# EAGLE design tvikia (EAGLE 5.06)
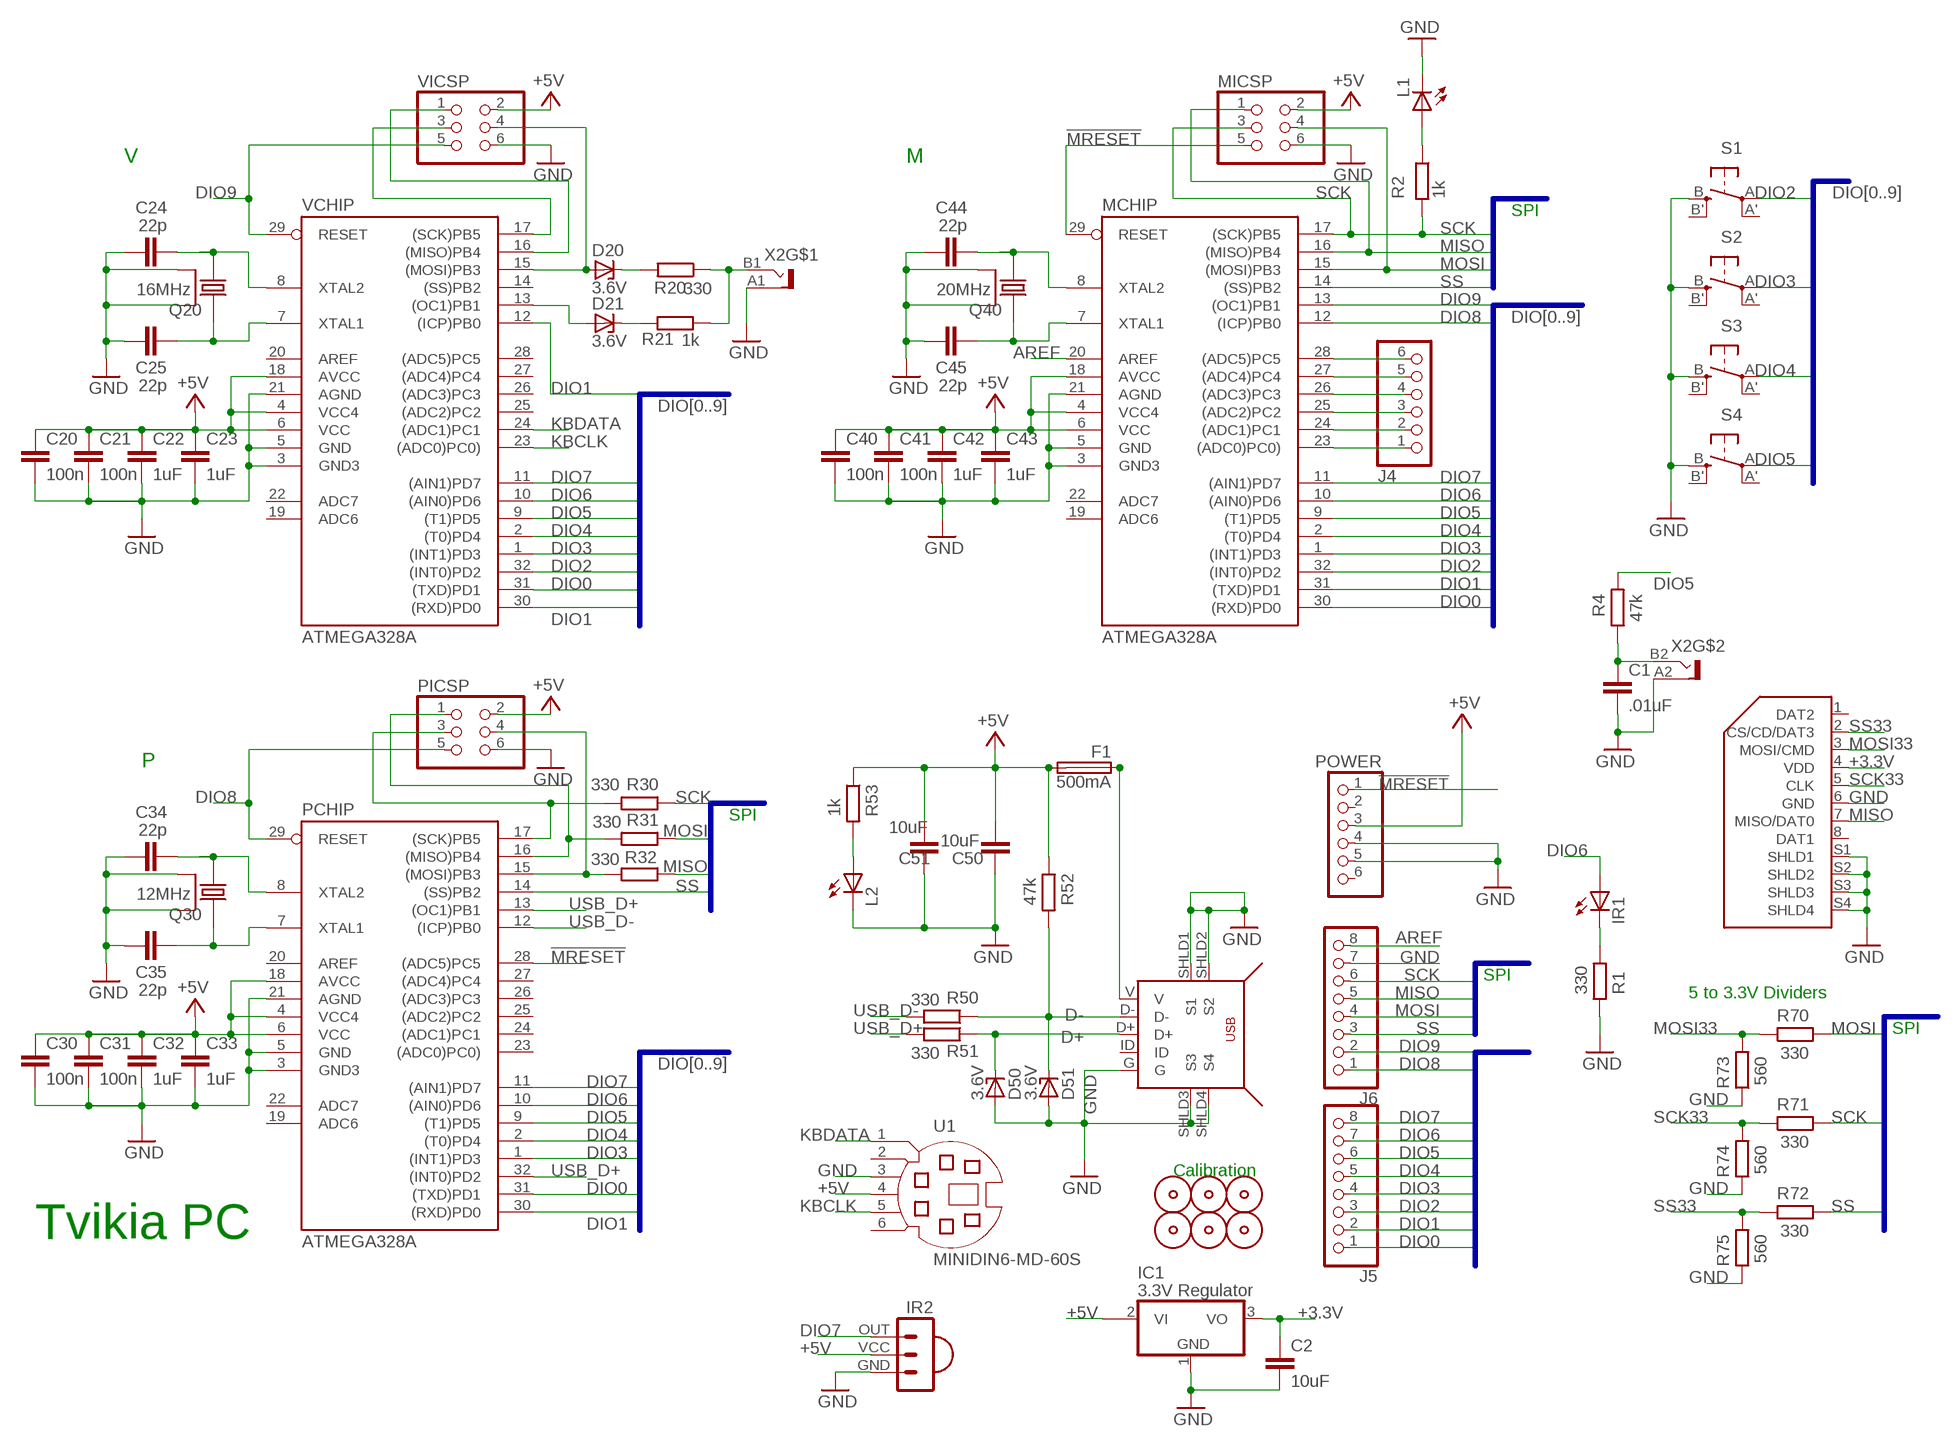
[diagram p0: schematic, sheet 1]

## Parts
C1  .01uF  C-EUC0603  [C0603]
C2  10uF  C-EUC0603  [C0603]
C20  100n  C-EUC0603  [C0603]
C21  100n  C-EUC0603  [C0603]
C22  1uF  C-EUC0603  [C0603]
C23  1uF  C-EUC0603  [C0603]
C24  22p  C-EUC0603  [C0603]
C25  22p  C-EUC0603  [C0603]
C30  100n  C-EUC0603  [C0603]
C31  100n  C-EUC0603  [C0603]
C32  1uF  C-EUC0603  [C0603]
C33  1uF  C-EUC0603  [C0603]
C34  22p  C-EUC0603  [C0603]
C35  22p  C-EUC0603  [C0603]
C40  100n  C-EUC0603  [C0603]
C41  100n  C-EUC0603  [C0603]
C42  1uF  C-EUC0603  [C0603]
C43  1uF  C-EUC0603  [C0603]
C44  22p  C-EUC0603  [C0603]
C45  22p  C-EUC0603  [C0603]
C50  10uF  C-EUC0603  [C0603]
C51  10uF  C-EUC0603  [C0603]
D20  3.6V  ZENER-DIODESOT23  [SOT23]
D21  3.6V  ZENER-DIODESOT23  [SOT23]
D50  3.6V  ZENER-DIODESOT23  [SOT23]
D51  3.6V  ZENER-DIODESOT23  [SOT23]
F1  500mA  FUSE0402  [0402]
IC1  3.3V Regulator  MCP170312MB  [SOT89]
IR1  LED5MM  [LED5MM]
IR2  IR-RECV-TSOP323  [IR-RECV-TSOP323]
J4  PINHD-1X6-CIRC  [1X06]
J5  PINHD-1X8-CIRC  [1X08]
J6  PINHD-1X8-CIRC  [1X08]
L1  LEDCHIP-LED0603  [CHIP-LED0603]
L2  LEDCHIPLED_0603  [CHIPLED_0603]
MCHIP  ATMEGA328A  [TQFP32-08]
MICSP  PINHD-2X3  [2X03]
PCHIP  ATMEGA328A  [TQFP32-08]
PICSP  PINHD-2X3  [2X03]
POWER  PINHD-1X6-CIRC  [1X06]
Q20  16MHz  NX3225SA  [NX3225SA]
Q30  12MHz  NX3225SA  [NX3225SA]
Q40  20MHz  NX3225SA  [NX3225SA]
R1  330  R-EU_R0603  [R0603]
R2  1k  R-EU_R0603  [R0603]
R4  47k  R-EU_R0603  [R0603]
R20  330  R-EU_R0603  [R0603]
R21  1k  R-EU_R0603  [R0603]
R30  330  R-EU_R0603  [R0603]
R31  330  R-EU_R0603  [R0603]
R32  330  R-EU_R0603  [R0603]
R50  330  R-EU_R0603  [R0603]
R51  330  R-EU_R0603  [R0603]
R52  47k  R-EU_R0603  [R0603]
R53  1k  R-EU_R0603  [R0603]
R70  330  R-EU_R0603  [R0603]
R71  330  R-EU_R0603  [R0603]
R72  330  R-EU_R0603  [R0603]
R73  560  R-EU_R0603  [R0603]
R74  560  R-EU_R0603  [R0603]
R75  560  R-EU_R0603  [R0603]
S1  EVQ-Q2P02W  [EVQ-Q2P02W]
S2  EVQ-Q2P02W  [EVQ-Q2P02W]
S3  EVQ-Q2P02W  [EVQ-Q2P02W]
S4  EVQ-Q2P02W  [EVQ-Q2P02W]
U1  MINIDIN6-MD-60S  [MINIDIN6-MD-60S]
U$1  CALIBRATION-MARK  [CALIBRATION-MARK]
U$4  CALIBRATION-MARK  [CALIBRATION-MARK]
U$5  CALIBRATION-MARK  [CALIBRATION-MARK]
U$6  CALIBRATION-MARK  [CALIBRATION-MARK]
U$8  MICROUSB-ZX62-B-5PA  [MICROUSB-ZX62-B-5PA]
U$9  MICROSD_3M_2900  [MICROSD_3M_2900]
U$10  CALIBRATION-MARK  [CALIBRATION-MARK]
U$12  CALIBRATION-MARK  [CALIBRATION-MARK]
VCHIP  ATMEGA328A  [TQFP32-08]
VICSP  PINHD-2X3  [2X03]
X2  DUAL-PHONO-161-4218-E  [DUAL-PHONO-161-4218-E]

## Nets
!MRESET: MCHIP.29(RESET) MICSP.5 PCHIP.28((ADC5)PC5) POWER.1
+3.3V: C2.1 IC1.3(VO) U$9.4(VDD)
+5V: C20.1 C21.1 C22.1 C23.1 C30.1 C31.1 C32.1 C33.1 C40.1 C41.1 C42.1 C43.1 C50.1 C51.1 F1.2 IC1.2@1(VI1) IR2.VCC MCHIP.4(VCC4) MCHIP.6(VCC) MCHIP.18(AVCC) MICSP.2 PCHIP.4(VCC4) PCHIP.6(VCC) PCHIP.18(AVCC) PICSP.2 POWER.3 R52.1 R53.1 U1.4 VCHIP.4(VCC4) VCHIP.6(VCC) VCHIP.18(AVCC) VICSP.2
AREF: J6.8 MCHIP.20(AREF)
D+: D50.3(C) R51.1 U$8.D+
D-: D51.3(C) R50.1 R52.2 U$8.D-
DIO0: J5.1 MCHIP.30((RXD)PD0) PCHIP.31((TXD)PD1) VCHIP.31((TXD)PD1)
DIO1: J5.2 MCHIP.31((TXD)PD1) PCHIP.30((RXD)PD0) VCHIP.12((ICP)PB0) VCHIP.30((RXD)PD0)
DIO2: J5.3 MCHIP.32((INT0)PD2) S1.A(P) VCHIP.32((INT0)PD2)
DIO3: J5.4 MCHIP.1((INT1)PD3) PCHIP.1((INT1)PD3) S2.A(P) VCHIP.1((INT1)PD3)
DIO4: J5.5 MCHIP.2((T0)PD4) PCHIP.2((T0)PD4) S3.A(P) VCHIP.2((T0)PD4)
DIO5: J5.6 MCHIP.9((T1)PD5) PCHIP.9((T1)PD5) R4.2 S4.A(P) VCHIP.9((T1)PD5)
DIO6: IR1.A J5.7 MCHIP.10((AIN0)PD6) PCHIP.10((AIN0)PD6) VCHIP.10((AIN0)PD6)
DIO7: IR2.OUT J5.8 MCHIP.11((AIN1)PD7) PCHIP.11((AIN1)PD7) VCHIP.11((AIN1)PD7)
DIO8: J6.1 MCHIP.12((ICP)PB0) PCHIP.29(RESET) PICSP.5
DIO9: J6.2 MCHIP.13((OC1)PB1) VCHIP.29(RESET) VICSP.5
GND [power]: C1.2 C2.2 C20.2 C21.2 C22.2 C23.2 C24.1 C25.1 C30.2 C31.2 C32.2 C33.2 C34.1 C35.1 C40.2 C41.2 C42.2 C43.2 C44.1 C45.1 C50.2 C51.2 D50.1(A) D51.1(A) IC1.1(GND) IR2.GND J6.7 L1.C L2.C MCHIP.3(GND3) MCHIP.5(GND) MCHIP.21(AGND) MICSP.6 PCHIP.3(GND3) PCHIP.5(GND) PCHIP.21(AGND) PICSP.6 POWER.4 POWER.5 Q20.2(GND2) Q20.4(GND) Q30.2(GND2) Q30.4(GND) Q40.2(GND2) Q40.4(GND) R1.2 R73.1 R74.1 R75.1 S1.B(S) S2.B(S) S3.B(S) S4.B(S) U1.3 U$8.G U$8.SHLD1(S1) U$8.SHLD2(S2) U$8.SHLD3(S3) U$8.SHLD4(S4) U$9.6(GND) U$9.S1(SHLD1) U$9.S2(SHLD2) U$9.S3(SHLD3) U$9.S4(SHLD4) VCHIP.3(GND3) VCHIP.5(GND) VCHIP.21(AGND) VICSP.6 X2.A1 X2.A2
KBCLK: U1.5 VCHIP.23((ADC0)PC0))
KBDATA: U1.1 VCHIP.24((ADC1)PC1)
MISO: J6.5 MCHIP.16((MISO)PB4) MICSP.1 R32.1 U$9.7(MISO/DAT0)
MOSI: J6.4 MCHIP.15((MOSI)PB3) MICSP.4 R31.1 R70.2
MOSI33: R70.1 R73.2 U$9.3(MOSI/CMD)
N$2: IR1.K(C) R1.1
N$3: L2.A R53.2
N$4: C34.2 PCHIP.8(XTAL2) Q30.1
N$5: C1.1 R4.1 X2.B2
N$8: F1.1 U$8.V
N$9: VCHIP.16((MISO)PB4) VICSP.1
N$10: C24.2 Q20.1 VCHIP.8(XTAL2)
N$11: C25.2 Q20.3 VCHIP.7(XTAL1)
N$12: D20.3(C) R20.2
N$13: D21.1(A) VCHIP.13((OC1)PB1)
N$14: D21.3(C) R21.1
N$15: R20.1 R21.2 X2.B1
N$23: C35.2 PCHIP.7(XTAL1) Q30.3
N$24: VCHIP.17((SCK)PB5) VICSP.3
N$28: C44.2 MCHIP.8(XTAL2) Q40.1
N$29: C45.2 MCHIP.7(XTAL1) Q40.3
N$30: J4.1 MCHIP.23((ADC0)PC0))
N$31: J4.2 MCHIP.24((ADC1)PC1)
N$32: J4.3 MCHIP.25((ADC2)PC2)
N$33: J4.4 MCHIP.26((ADC3)PC3)
N$34: J4.5 MCHIP.27((ADC4)PC4)
N$35: J4.6 MCHIP.28((ADC5)PC5)
N$37: L1.A R2.1
PIXEL1: D20.1(A) VCHIP.15((MOSI)PB3) VICSP.4
PMISO: PCHIP.15((MOSI)PB3) PICSP.4 R32.2
PMOSI: PCHIP.16((MISO)PB4) PICSP.1 R31.2
PSCK: PCHIP.17((SCK)PB5) PICSP.3 R30.2
SCK: J6.6 MCHIP.17((SCK)PB5) MICSP.3 R2.2 R30.1 R71.2
SCK33: R71.1 R74.2 U$9.5(CLK)
SS: J6.3 MCHIP.14((SS)PB2) PCHIP.14((SS)PB2) R72.2
SS33: R72.1 R75.2 U$9.2(CS/CD/DAT3)
USB_D+: PCHIP.13((OC1)PB1) PCHIP.32((INT0)PD2) R51.2
USB_D-: PCHIP.12((ICP)PB0) R50.2
Unconnected: IC1.2(VI) MCHIP.19(ADC6) MCHIP.22(ADC7) PCHIP.19(ADC6) PCHIP.20(AREF) PCHIP.22(ADC7) PCHIP.23((ADC0)PC0)) PCHIP.24((ADC1)PC1) PCHIP.25((ADC2)PC2) PCHIP.26((ADC3)PC3) PCHIP.27((ADC4)PC4) POWER.2 POWER.6 S1.A'(P1) S1.B'(S1) S2.A'(P1) S2.B'(S1) S3.A'(P1) S3.B'(S1) S4.A'(P1) S4.B'(S1) U1.2 U1.6 U$8.ID U$9.1(DAT2) U$9.8(DAT1) VCHIP.14((SS)PB2) VCHIP.19(ADC6) VCHIP.20(AREF) VCHIP.22(ADC7) VCHIP.25((ADC2)PC2) VCHIP.26((ADC3)PC3) VCHIP.27((ADC4)PC4) VCHIP.28((ADC5)PC5)

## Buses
DIO[0..9]
SPI:SCK,MOSI,MISO,SS

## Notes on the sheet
- V | M
- SPI
- P
- SPI
- SPI
- 5 to 3.3V Dividers
- SPI
- Calibration
- Tvikia PC

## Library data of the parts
C1 C2 C20-C25 C30-C35 C40-C45 C50 C51 = rcl:C-EU: CAPACITOR, European symbol
D20 D21 D50 D51 = diode:ZENER-DIODE: Z-Diode
F1 = tvikia:FUSE0402
IC1 = linear:MCP1703*: 250 mA, 16V, Low Quiescent Current LDO Regulator Source: http://ww1.microchip.com/downloads/en/DeviceDoc/22049b.pdf
IR1 L1 L2 = led:LED: LED
IR2 = tvikia:IR-RECV-TSOP323
J4 POWER = tvikia:PINHD-1X6-CIRC: PIN HEADER
J5 J6 = tvikia:PINHD-1X8-CIRC: PIN HEADER
MCHIP PCHIP VCHIP = tvikia:ATMEGA328: MICROCONTROLLER 4 Kbytes FLASH 128 bytes SRAM 256 bytes EEPROM UART 6-channel 10 bit ADC
MICSP PICSP VICSP = pinhead:PINHD-2X3: PIN HEADER
Q20 Q30 Q40 = tvikia:NX3225SA
R1 R2 R4 R20 R21 R30-R32 R50-R53 R70-R75 = rcl:R-EU_: RESISTOR, European symbol
S1-S4 = tvikia:EVQ-Q2P02W
U1 = tvikia:MINIDIN6-MD-60S
U$1 U$4-U$6 U$10 U$12 = tvikia:CALIBRATION-MARK: Calibration mark for board pick-n-place.
U$8 = tvikia:MICROUSB-ZX62-B-5PA
U$9 = tvikia:MICROSD_3M_2900
X2 = tvikia:DUAL-PHONO-161-4218-E

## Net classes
0 default: width 0.203 mm, drill 0.305 mm, clearance 0.203 mm
1 power: width 0.356 mm, drill 0.305 mm, clearance 0.203 mm
2 gnd: width 0.356 mm, drill 0.305 mm, clearance 0.203 mm

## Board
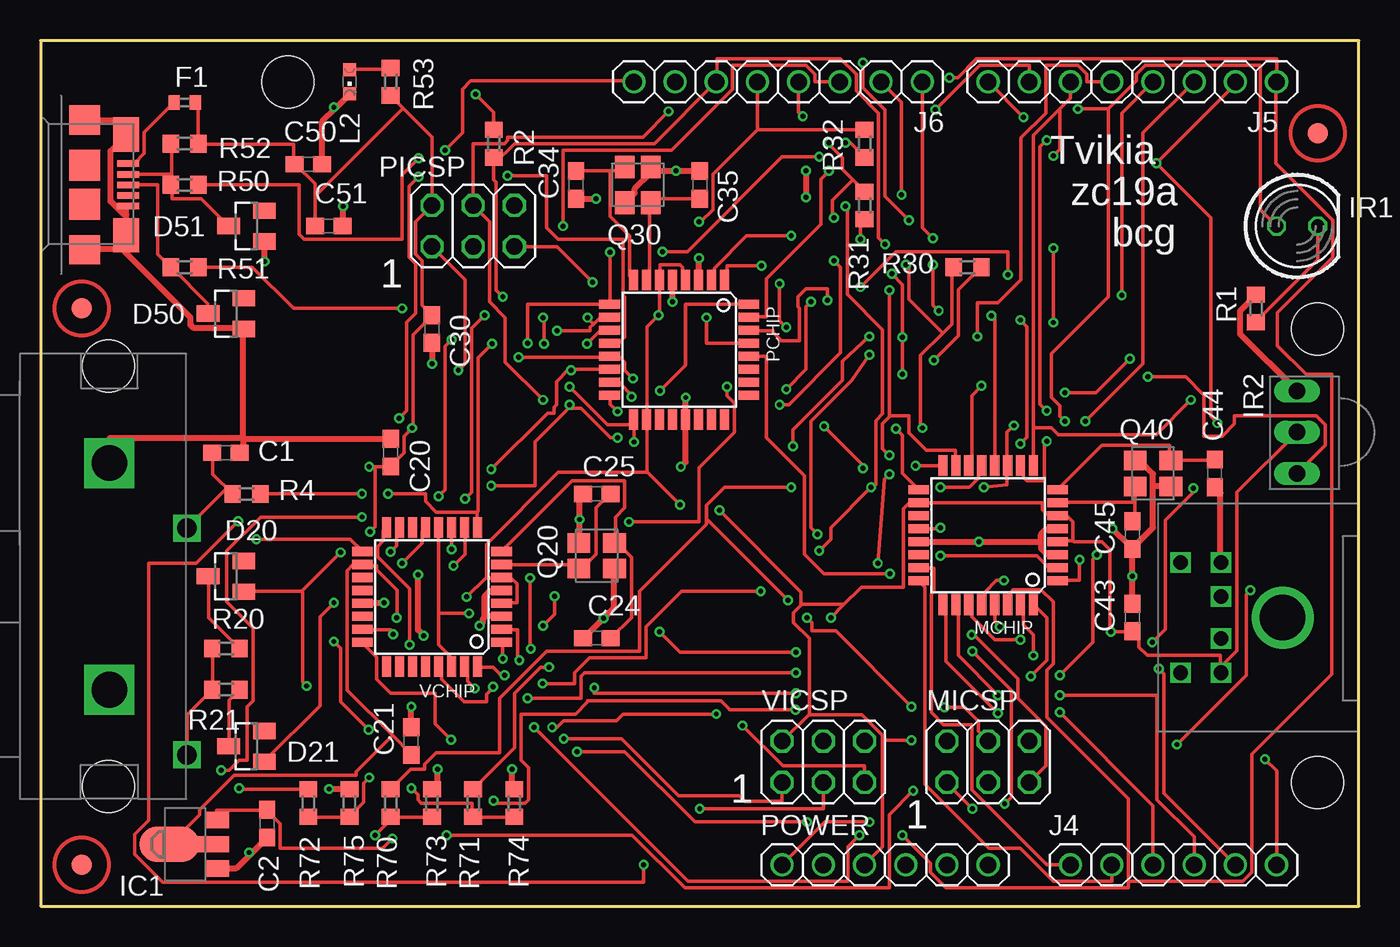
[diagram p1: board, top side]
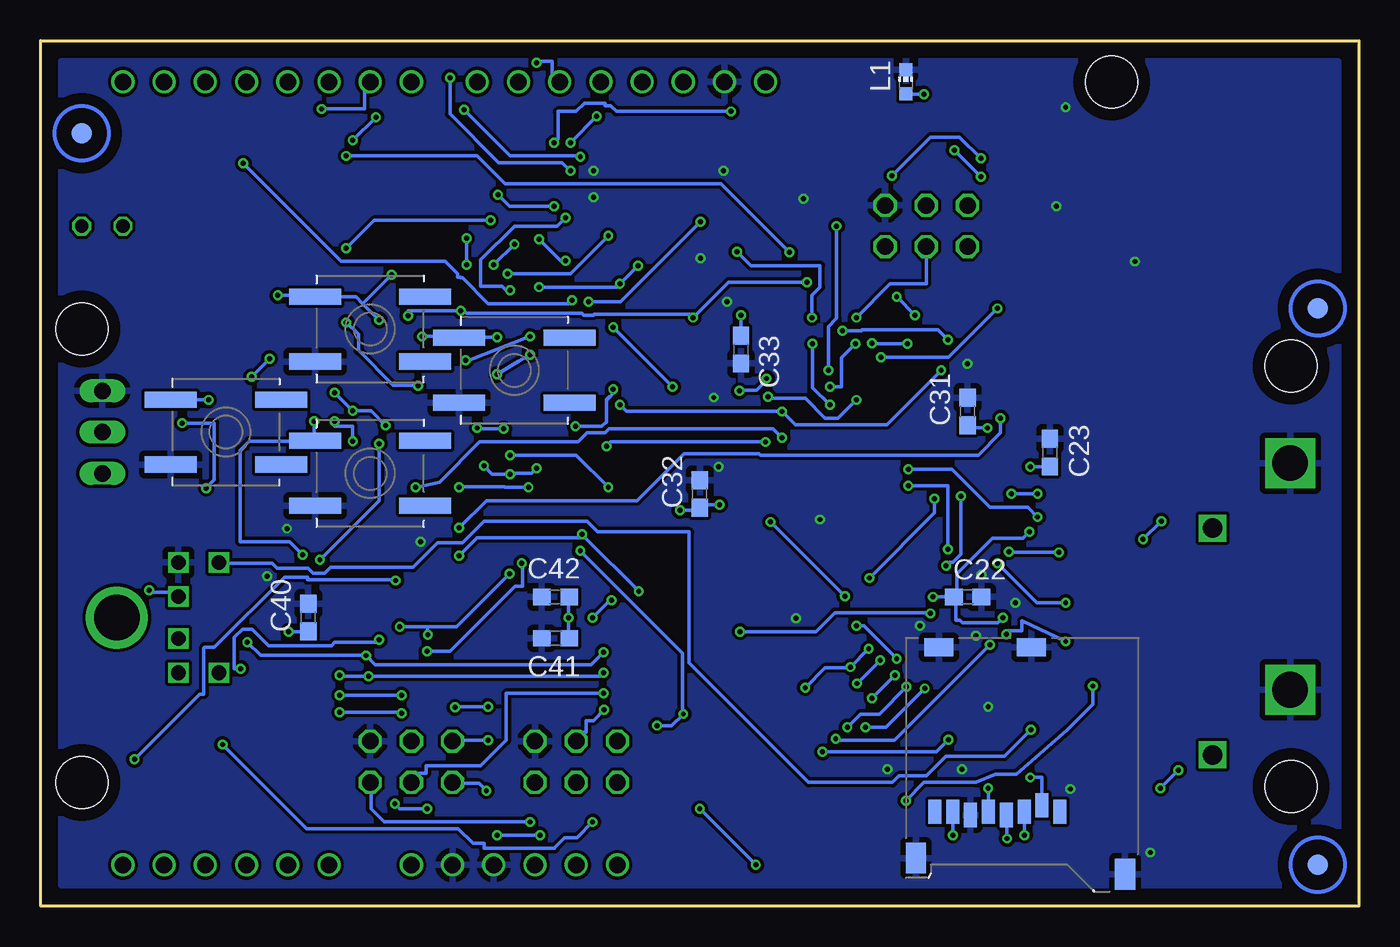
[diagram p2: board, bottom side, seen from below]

Size 81.28 x 53.34 mm. Coordinates in mm from the lower left corner, seen from the top.
Outline: 0,0 81.28,0 81.28,53.34 0,53.34 0,0
Copper layers (1*16): Top 0.035mm / dielectric 1.5mm / Bottom 0.035mm
Design rules "chung_nam_design_rules *": minimum track width 8mil, minimum drill 12mil, track to track 8mil, track to pad 8mil, pad to pad 5mil, via to via 15mil, smd to smd 5mil, copper to edge 30mil, drill to drill 30mil, minimum pad ring 7mil, minimum via ring 6mil, stop-mask expansion 3mil, vias tented up to drill 0mil, thermal gap 14mil
Holes 3.2 mm at 15.24,50.8 78.74,35.56 78.74,7.62

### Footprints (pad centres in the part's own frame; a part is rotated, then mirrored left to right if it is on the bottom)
C0603 = smd 1.1 x 1: 1 -0.85,0; 2 0.85,0
SOT23 = smd 1 x 1.4: 1 -0.95,-1.1; 2 0.95,-1.1; 3 0,1.1
0402 = smd 0.7 x 0.9: 1 -0.65,0; 2 0.65,0
SOT89 = smd 1 x 1.5: 1 -1.499,-1.981; 3 1.499,-1.981 | smd 1 x 2: 2 0,-1.727 | smd 2.2 x 3.7: 2@1 0,0.94
LED5MM = drill 0.813 octagon: A -1.27,0; K 1.27,0
IR-RECV-TSOP323 = drill 1.016 long: GND -2.54,0; OUT 2.54,0; VCC 0,0
1X06 = drill 1.016 round: 1 -6.35,0; 2 -3.81,0; 3 -1.27,0; 4 1.27,0; 5 3.81,0; 6 6.35,0
1X08 = drill 1.016 round: 1 -8.89,0; 2 -6.35,0; 3 -3.81,0; 4 -1.27,0; 5 1.27,0; 6 3.81,0; 7 6.35,0; 8 8.89,0
CHIP-LED0603 = smd 0.8 x 0.8: A 0,-0.75; C 0,0.75
CHIPLED_0603 = smd 0.8 x 0.8: A 0,-0.75; C 0,0.75
TQFP32-08 = smd 1.27 x 0.559: 1 -4.293,2.8; 2 -4.293,2; 3 -4.293,1.2; 4 -4.293,0.4; 5 -4.293,-0.4; 6 -4.293,-1.2; 7 -4.293,-2; 8 -4.293,-2.8; 17 4.293,-2.8; 18 4.293,-2; 19 4.293,-1.2; 20 4.293,-0.4; 21 4.293,0.4; 22 4.293,1.2; 23 4.293,2; 24 4.293,2.8 | smd 0.559 x 1.27: 9 -2.8,-4.293; 10 -2,-4.293; 11 -1.2,-4.293; 12 -0.4,-4.293; 13 0.4,-4.293; 14 1.2,-4.293; 15 2,-4.293; 16 2.8,-4.293; 25 2.8,4.293; 26 2,4.293; 27 1.2,4.293; 28 0.4,4.293; 29 -0.4,4.293; 30 -1.2,4.293; 31 -2,4.293; 32 -2.8,4.293
2X03 = drill 1.016 octagon: 1 -2.54,-1.27; 2 -2.54,1.27; 3 0,-1.27; 4 0,1.27; 5 2.54,-1.27; 6 2.54,1.27
NX3225SA = smd 1.4 x 1.2: 1 -1.1,-0.8; 2 1.1,-0.8; 3 1.1,0.8; 4 -1.1,0.8
R0603 = smd 1 x 1.1: 1 -0.85,0; 2 0.85,0
EVQ-Q2P02W = smd 3.2 x 1: A -3.4,2; A' 3.4,2; B -3.4,-2; B' 3.4,-2
MINIDIN6-MD-60S = drill 0.9 square: 1 -1.3,-8.5; 2 1.3,-8.5; 3 -3.4,-8.5; 4 3.4,-8.5; 5 -3.4,-11; 6 3.4,-11 | drill 2.8 round: P$7 0,-4.7
CALIBRATION-MARK = smd 1.27 x 1.27: P$1 0,0
MICROUSB-ZX62-B-5PA = smd 0.4 x 1.35: D+ 0,4.13; D- -0.65,4.13; G 1.3,4.13; ID 0.65,4.13; V -1.3,4.13 | smd 1.9 x 1.9: P$8 1.2,1.45; P$9 -1.2,1.45 | smd 2.1 x 1.6: SHLD1 -3.1,4; SHLD2 3.1,4 | smd 1.8 x 1.9: SHLD3 -4,1.45; SHLD4 4,1.45
MICROSD_3M_2900 = smd 0.8 x 1.5: 1 -9.5,10.7; 2 -8.4,10.3; 3 -7.3,10.7; 4 -6.2,10.9; 5 -5.1,10.7; 6 -4,10.9; 7 -2.9,10.7; 8 -1.8,10.7 | smd 1.24 x 1.9: S1 -13.52,14.55; S2 -0.62,13.55 | smd 1.8 x 1.1: S3 -7.75,0.55; S4 -2.05,0.55
DUAL-PHONO-161-4218-E = drill 2.2 square: A1 -6.985,-5.512; A2 6.985,-5.512 | drill 1.2 square: B1 -10.998,-10.287; B2 2.972,-10.287 | hole 3.2: -12.954,-5.461; 12.954,-5.461

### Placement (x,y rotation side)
C1  11.43,27.94 0 top
C2  13.97,5.08 270 top
C20  21.59,27.94 90 top
C21  22.86,10.16 90 top
C22  24.13,19.05 0 bottom
C23  19.05,27.94 90 bottom
C24  34.29,16.51 0 top
C25  34.29,25.4 0 top
C30  24.13,35.56 270 top
C31  24.13,30.48 90 bottom
C32  40.64,25.4 90 bottom
C33  38.1,34.29 270 bottom
C34  33.02,44.45 90 top
C35  40.64,44.45 270 top
C40  64.77,17.78 90 bottom
C41  49.53,16.51 180 bottom
C42  49.53,19.05 180 bottom
C43  67.31,17.78 90 top
C44  72.39,26.67 90 top
C45  67.31,22.86 90 top
C50  16.51,45.72 0 top
C51  17.78,41.91 0 top
D20  11.43,20.32 90 top
D21  12.7,9.84 90 top
D50  11.43,36.51 90 top
D51  12.7,41.91 90 top
F1  8.89,49.53 0 top
IC1  8.89,3.81 90 top
IR1  77.47,41.91 0 top
IR2  77.47,29.21 270 top
J4  69.85,2.54 0 top
J5  67.31,50.8 180 top
J6  45.47,50.8 180 top
L1  27.94,50.8 0 bottom
L2  19.05,50.8 180 top
MCHIP  58.42,22.86 180 top
MICSP  58.42,8.89 0 top
PCHIP  39.37,34.29 270 top
PICSP  26.67,41.91 0 top
POWER  52.07,2.54 0 top
Q20  34.29,21.59 180 top
Q30  36.83,44.45 270 top
Q40  68.58,26.67 180 top
R1  74.93,36.83 90 top
R2  27.94,46.99 270 top
R4  12.7,25.4 0 top
R20  11.43,15.88 0 top
R21  11.43,13.34 180 top
R30  57.15,39.37 0 top
R31  50.8,43.18 270 top
R32  50.8,46.99 270 top
R50  8.89,44.45 0 top
R51  8.89,39.37 0 top
R52  8.89,46.99 180 top
R53  21.59,50.8 90 top
R70  21.59,6.35 90 top
R71  26.67,6.35 90 top
R72  16.51,6.35 90 top
R73  24.13,6.35 270 top
R74  29.21,6.35 270 top
R75  19.05,6.35 270 top
S1  60.96,26.67 0 bottom
S2  60.96,35.56 0 bottom
S3  52.07,33.02 0 bottom
S4  69.85,29.21 0 bottom
U1  81.28,17.78 270 top
U$1  78.74,47.62 0 bottom
U$4  2.54,2.54 0 top
U$5  78.74,47.62 0 top
U$6  2.54,36.83 0 top
U$8  1.27,44.45 270 top
U$9  27.94,16.51 180 bottom
U$10  2.54,2.54 0 bottom
U$12  2.54,36.83 0 bottom
VCHIP  24.13,19.05 180 top
VICSP  48.26,8.89 0 top
X2  -1.27,20.32 90 top

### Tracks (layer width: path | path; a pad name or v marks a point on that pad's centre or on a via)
!MRESET  (via drill 0.3)
  Top 0.203: POWER.1 48.36,5.18 v51.1,5.18 | v52.38,20.47 48.31,20.47 47.09,21.69 47.09,26.52 44.76,28.85 44.76,33.88 43.69,33.88 PCHIP.28 | v59.13,17.22 58.83,17.53 58.83,18.54 MCHIP.29 | MICSP.5 61.98,8.64 61.98,11.07 60.25,12.8 60.25,14.02 57.56,16.71 v57.4,16.71
  Bottom 0.203: v51.1,5.18 60.1,5.18 60.91,5.99 60.91,7.62 MICSP.5 | v52.38,20.47 55.63,17.22 57.4,17.22 | 57.4,17.22 v59.13,17.22 | v57.4,16.71 57.4,17.22
+3.3V  (via drill 0.3)
  Top 0.203: IC1.3 10.87,5.33 10.87,5.89 13.97,5.89 C2.1 14.02,5.84 14.78,5.08 14.78,3.56 21.08,3.56 v21.69,4.17
  Bottom 0.203: v21.69,4.17 21.69,5.59 U$9.4
+5V  (via drill 0.3)
  Top 0.203: 20.62,27.08 21.59,27.08 C20.1 21.64,27.18 22.4,27.94 22.4,28.96 v22.91,29.46 22.96,29.52 22.96,35.2 24.13,36.37 C30.1 24.08,36.47 23.52,37.03 23.52,39.78 23.11,40.18 23.11,42.16 PICSP.2 24.13,47.4 22.35,49.17 | 20.62,27.08 v20.27,27.08 | 22.35,49.17 21.59,49.94 R53.1 | F1.2 9.7,49.38 9.7,46.99 R52.1 9.8,46.94 15.6,46.94 15.6,45.77 C50.1 15.7,45.72 16.92,44.5 16.92,43.79 | 16.92,43.79 16.92,41.91 C51.1 | 22.35,49.17 16.97,43.79 16.92,43.79 | 21.69,10.52 18.9,13.31 18.9,20.68 19.25,21.03 19.81,21.03 VCHIP.18 19.91,20.98 20.73,20.98 20.73,20.73 22,19.46 22,17.83 v21.95,17.78 | 21.69,10.52 22.86,9.35 C21.1 | IC1.2@1 7.98,3.81 9.8,5.64 9.8,5.94 11.94,8.08 19.46,8.08 19.46,8.28 21.69,10.52 | PCHIP.4 39.73,38.61 39.57,38.76 39.57,39.37 39.42,39.52 38.2,39.52 38.2,38.66 PCHIP.6 38.15,38.56 38.15,36.47 v38.1,36.42 37.39,35.71 37.39,30.07 PCHIP.18 37.39,29.97 37.39,26.77 | v26.26,19.05 27.43,20.22 | 27.43,20.22 28.4,20.22 VCHIP.6 28.5,20.22 29.01,20.22 29.36,19.86 29.36,18.69 28.45,18.69 VCHIP.4 | 37.39,26.77 v39.42,24.74 | 27.43,20.22 27.48,20.27 27.48,22.3 31.9,26.72 37.34,26.72 37.39,26.77 | IR2.VCC 73.76,25.5 73.76,15.75 72.8,14.78 U1.4 72.75,14.43 72.75,15.44 68.22,15.44 67.72,15.95 67.72,16.51 67.36,16.87 C43.1 67.31,16.92 v65.99,16.92 65.94,16.97 65.94,21.95 65.43,22.45 63.7,22.45 63.65,22.5 | 63.65,22.5 62.74,22.5 MCHIP.4 | 63.65,22.5 63.65,23.67 63.3,24.03 62.74,24.03 MCHIP.6 62.64,24.08 62.13,24.08 61.77,24.43 61.77,24.84 54.15,24.84 MCHIP.18 54.05,24.79 53.49,24.79 53.19,24.49 53.19,19.66 50.6,19.66 49.48,18.54 | 49.48,18.54 v48.72,17.78
  Top 0.203: 47.4,11.84 VICSP.2 | 47.4,11.84 47.4,16.51 46.43,17.48 46.43,18.09 46.94,18.59 | 46.94,18.59 49.43,18.59 49.48,18.54 | POWER.3 51.92,3.66 51.92,10.21 | 51.92,10.21 51.92,10.52 50.65,11.79 47.45,11.79 47.4,11.84 | 51.92,10.21 v53.7,10.21 | v41.86,24.38 46.89,19.36 46.89,18.64 46.94,18.59 | v20.32,23.06 20.62,23.37 20.62,27.08
  Bottom 0.203: v20.27,27.08 19.05,27.08 C23.1 | v22.91,29.46 23.98,29.46 24.13,29.62 C31.1 | v38.1,36.42 C33.1 | C22.1 v26.26,19.05 | v39.42,24.74 40.49,24.74 40.64,24.59 C32.1 40.69,24.49 40.79,24.38 v41.86,24.38 | v65.99,16.92 64.77,16.92 C40.1 | C41.1 48.72,16.51 v48.72,17.78 48.72,19.05 C42.1 | MICSP.2 55.83,10.21 v53.7,10.21 | v21.95,17.78 22.25,17.48 24.43,17.48 24.59,17.63 24.84,17.63 24.84,19 24.89,19 C22.1 | v20.32,23.06 20.73,22.66 22.61,22.66 24.79,20.47 24.79,19.05 C22.1
AREF  (via drill 0.3)
  Top 0.203: v55.47,23.32 55.47,23.27 54.15,23.27 MCHIP.20 | v22.1,30.07 22.55,30.53 22.55,35.97 23.11,36.52 23.11,39.57 22.71,39.98 22.71,44.35 v23.32,44.96 | v24.94,46.58 26.01,47.65 26.01,50.34 26.52,50.85 36.58,50.85 J6.8
  Bottom 0.203: v55.47,23.32 53.8,24.99 44.5,24.99 41.6,27.89 36.98,27.89 36.88,27.79 23.47,27.79 22.1,29.16 v22.1,30.07 | v23.32,44.96 v24.94,46.58
D+
  Top 0.203: D50.3 10.31,36.52 10.31,37.13 8.08,39.37 R51.1 7.98,39.42 7.21,40.18 7.21,44.45 U$8.D+
D-
  Top 0.203: 8.08,45.11 8.08,46.99 R52.2 | 8.08,45.11 8.08,44.45 R50.1 8.13,44.4 8.13,43.59 9.91,43.59 11.58,41.91 D51.3 | U$8.D- 5.44,45.11 8.08,45.11
DIO0  (via drill 0.3)
  Top 0.203: v48.62,45.31 48.11,44.81 48.11,42.01 44.76,38.66 44.76,36.32 43.69,36.32 PCHIP.31 | v56.03,51.05 56.54,51.05 57.71,52.22 76.2,52.22 J5.1 76.15,50.75 76.15,45.77 79.65,42.27 79.65,39.98 76.25,36.58 76.25,34.54 78.03,32.77 79.6,32.77 79.6,14.28 74.68,9.35 74.68,2.08 74.12,1.52 67.06,1.52 | v26.77,13.41 26.31,13.87 26.31,14.58 26.16,14.73 VCHIP.31 | v30.43,11.02 39.93,1.52 49.78,1.52 49.78,3.66 v50.49,4.37 | v53.14,4.37 54.86,2.64 54.86,2.08 55.83,1.12 67.06,1.12 67.06,1.52 | 67.06,1.52 67.06,6.6 62.03,11.63 62.03,14.53 62.43,14.94 62.43,18.75 61.67,19.51 59.94,19.51 59.94,19.46 59.64,19.15 59.64,18.59 MCHIP.30
  Bottom 0.203: v48.62,45.31 49.12,45.82 53.03,45.82 56.03,48.82 v56.03,51.05 | v26.77,13.41 29.16,11.02 v30.43,11.02 | v50.49,4.37 v53.14,4.37
DIO1  (via drill 0.3)
  Top 0.203: 24.54,18.03 24.54,16.1 25.3,15.34 25.3,14.78 VCHIP.30 | 24.54,18.03 24.54,23.32 VCHIP.12 | v48.51,37.34 48.51,38.05 47.19,38.05 46.69,37.54 46.69,36.93 46.79,36.83 46.79,34.85 45.67,34.85 45.16,35.36 45.16,35.46 43.69,35.46 PCHIP.30 | J5.2 73.66,50.65 v68.78,45.77 72.14,42.42 72.14,30.18 v72.54,29.77 | v61.21,15.44 61.21,16.71 60.6,17.32 60.6,18.39 60.45,18.54 MCHIP.31 | v68.53,16.26 69.34,17.07 69.34,23.77 71.07,25.5 v71.07,25.76 | v38.15,16.92 39.42,15.65 v46.58,15.65 | 24.54,18.03 v26.42,18.03
  Bottom 0.203: v48.51,37.34 48.72,37.13 53.7,37.13 55.27,38.71 55.37,38.71 55.37,38.76 55.58,38.76 55.58,38.96 56.34,39.73 62.74,39.73 v68.78,45.77 | v68.53,16.26 67.72,15.44 v61.21,15.44 60.66,14.88 47.35,14.88 v46.58,15.65 | v71.07,25.76 70.56,26.26 70.56,29.77 v72.54,29.77 | v26.42,18.03 26.47,18.09 32.31,18.09 33.48,16.92 v38.15,16.92
DIO2  (via drill 0.3)
  Top 0.203: J5.3 67.97,47.65 67.97,33.43 v64.41,29.87 | v28.6,14.22 28.4,14.22 27.89,14.73 26.98,14.73 VCHIP.32 | v30.02,12.8 33.33,12.8 33.33,14.17 33.53,14.38 v46.58,14.38 | v61.06,14.17 62.03,15.14 62.03,17.78 61.27,18.54 MCHIP.32 | v65.13,21.64 64.87,21.39 64.87,16.26 v62.84,14.22
  Bottom 0.203: v64.41,29.87 64.41,28.7 64.36,28.7 S1.A 64.47,28.65 68.43,28.65 68.99,28.09 68.99,22.45 65.94,22.45 v65.13,21.64 | v28.6,14.22 v30.02,12.8 | v46.58,14.38 46.79,14.17 v61.06,14.17 62.79,14.17 v62.84,14.22
DIO3  (via drill 0.3)
  Top 0.203: v28.5,15.24 28.5,16.15 28.45,16.2 VCHIP.1 | v30.99,17.27 31.7,17.98 v31.7,19.1 | v36.27,23.67 40.59,23.67 40.59,27.03 42.77,29.21 42.77,30.99 42.32,31.45 v42.32,32 | v45.97,35.66 45.57,36.07 v45.57,38.35 | v44.45,39.47 42.32,39.47 42.32,38.71 42.22,38.61 PCHIP.1 | v64.06,21.34 64.06,20.07 62.74,20.07 MCHIP.1 | v60.4,28.5 60.81,28.91 60.81,35.71 v60.4,36.12 | J5.4 66.65,48.87 v66.65,37.64 | v50.55,38.15 52.73,40.34 59.64,40.34 v59.64,38.91
  Bottom 0.203: v28.5,15.24 30.53,17.27 v30.99,17.27 | v31.7,19.1 v36.27,23.67 | v42.32,32 v45.97,35.66 | v44.45,39.47 v45.57,38.35 45.77,38.15 v50.55,38.15 | v64.06,21.34 60.4,24.99 v60.4,28.5 | 61.42,37.13 61.82,37.54 64.31,37.54 S2.A 64.41,37.64 v66.65,37.64 | 61.42,37.13 v60.4,36.12 | v59.64,38.91 61.42,37.13
DIO4  (via drill 0.3)
  Top 0.203: v29.52,15.14 29.41,15.24 29.41,17.02 28.45,17.02 VCHIP.2 | v30.94,13.72 32.92,13.72 32.92,14.38 33.83,15.29 37.34,15.29 37.34,17.22 39.52,19.41 v44.4,19.41 | v55.47,21.59 61.42,21.59 62.13,20.88 62.69,20.88 MCHIP.2 | v46.28,41.3 43.54,41.3 41.55,39.32 41.55,38.76 41.4,38.61 PCHIP.2 | v52.48,38.96 53.14,38.3 v53.14,35.05 v53.14,32.77 | J5.5 64.52,50.8 64.52,51.26 63.96,51.82 61.98,51.82 61.98,48.87 60.45,47.35 60.45,38.61 59.03,37.19 57.76,37.19 v57.76,35.1 | v47.9,22.91 47.5,23.32 47.5,29.87 49.99,32.36 v51.1,33.98
  Bottom 0.203: v29.52,15.14 v30.94,13.72 | v44.4,19.41 47.7,22.71 47.9,22.71 | 47.9,22.71 54.36,22.71 v55.47,21.59 | v46.28,41.3 48.62,38.96 v52.48,38.96 | v53.14,35.05 55.42,35.05 S3.A 55.52,35.1 v57.76,35.1 | v51.1,33.98 51.82,33.58 v53.14,32.77 | 47.9,22.71 v47.9,22.91
DIO5  (via drill 0.3)
  Top 0.203: v21.44,25.4 23.72,25.4 23.72,24.94 24.38,24.28 26.92,24.28 | 26.92,24.28 26.92,23.37 VCHIP.9 | R4.2 v19.81,25.4 | v30.02,34.7 30.02,37.08 35.05,37.08 PCHIP.9 35.1,37.19 v35.1,40.28 | v27.84,34.65 26.98,33.78 26.98,24.33 26.92,24.28 | 61.21,29.46 61.21,47.5 62.79,49.07 | 61.21,29.46 61.21,27.18 MCHIP.9 | 62.79,49.07 63.5,49.78 J5.6 | v70.92,31.19 68.78,29.06 62.74,29.06 62.33,29.46 61.21,29.46 | v62.43,46.23 62.84,46.63 62.84,49.02 62.79,49.07
  Bottom 0.203: v19.81,25.4 v21.44,25.4 | v30.02,34.7 29.97,34.65 v27.84,34.65 | v70.92,31.19 73.2,31.19 S4.A | v35.1,40.28 39.32,44.5 52.63,44.5 54.36,46.23 v62.43,46.23
DIO6  (via drill 0.3)
  Top 0.203: v25.45,20.98 26.16,21.69 26.16,23.32 VCHIP.10 | v24.54,25.25 24.94,25.65 24.94,34.49 v25.35,34.9 | v31.85,35.46 33.88,35.46 33.88,35.66 34.09,35.87 | 34.09,35.87 34.49,36.27 35.05,36.27 PCHIP.10 | v62.03,28.65 61.87,28.5 61.87,26.21 60.81,26.21 60.6,26.42 60.6,26.98 60.45,27.13 MCHIP.10 | v63.14,29.87 62.84,30.18 62.84,30.84 62.33,31.34 62.33,34.04 65.84,37.54 65.84,49.12 | 65.84,49.12 67.56,50.85 67.56,51.26 68.12,51.82 75.18,51.82 75.18,42.93 IR1.A | v63.96,49.12 65.84,49.12 | v33.73,36.27 33.73,36.22 34.09,35.87 | v38.35,40.34 39.88,40.34 45.72,46.18 v48.01,46.18 | v55.17,49.07 57.91,51.82 60.96,51.82 J5.7
  Bottom 0.203: v25.45,20.98 25.25,21.18 25.04,21.18 24.54,21.69 v24.54,25.25 | v25.35,34.9 25.96,35.51 30.63,35.51 30.68,35.46 v31.85,35.46 | v62.03,28.65 62.03,29.57 63.14,29.57 v63.14,29.87 | J5.7 60.96,50.19 61.32,50.19 61.32,49.12 v63.96,49.12 | v33.73,36.27 33.73,37.64 33.22,38.15 33.22,39.47 37.49,39.47 v38.35,40.34 | v48.01,46.18 48.06,46.23 52.32,46.23 v55.17,49.07
DIO7  (via drill 0.3)
  Top 0.203: v25.35,22 25.35,23.32 VCHIP.11 | v27.79,25.91 30.48,25.91 30.48,28.6 32.61,30.73 v32.61,30.89 32.66,30.68 33.33,30.68 35.15,28.85 v35.56,28.85 | v33.68,34.65 34.49,35.46 35.05,35.46 PCHIP.11 | v59.99,29.62 59.59,29.21 59.59,27.18 MCHIP.11 59.59,27.08 59.59,25.96 v58.17,25.81 | v62.03,30.53 61.62,30.94 61.62,46.79 v62.03,47.19 | v60.6,48.62 J5.8 | IR2.OUT 79.2,28.4 79.2,29.67 78.64,30.23 73.61,30.23 73.61,29.72 72.85,28.96 71.73,28.96 71.73,31.5 70.61,32.61 v68.28,32.61 | v67.16,33.73 65.08,31.65 v63.14,31.65
  Bottom 0.203: v25.35,22 25.35,25.91 v27.79,25.91 | v32.61,30.89 33.68,31.95 v33.68,34.65 | v59.99,29.62 60.91,30.53 v62.03,30.53 v63.14,31.65 | v62.03,47.19 v60.6,48.62 | v67.16,33.73 v68.28,32.61 | v35.56,28.85 36.12,29.41 46.23,29.41 46.48,29.16 47.6,29.16 48.16,28.6 54.2,28.6 56.69,26.11 58.06,25.81 58.12,25.76 v58.17,25.81
DIO8  (via drill 0.3)
  Top 0.203: v41.05,36.27 41.05,34.7 43.64,34.7 PCHIP.29 | v34.04,38.46 31.85,40.64 PICSP.5 | v58.62,36.37 58.83,36.17 58.83,27.18 MCHIP.12 | v55.37,36.68 55.02,37.03 v55.02,39.52 | v55.02,41.15 54.36,41.81 J6.1
  Bottom 0.203: v34.04,38.46 38.86,38.46 v41.05,36.27 41.25,36.47 47.14,36.47 47.19,36.42 47.8,36.42 47.9,36.52 55.02,36.52 55.12,36.63 55.32,36.63 v55.37,36.68 58.62,36.68 v58.62,36.37 | v55.02,39.52 v55.02,41.15
DIO9  (via drill 0.3)
  Top 0.203: v27.89,13.51 27.89,13.46 27.48,13.06 27.48,12.6 26.11,12.6 24.74,13.97 24.74,14.53 24.54,14.73 VCHIP.29 | v31.55,11.02 31.85,11.02 32.26,11.43 35.51,11.43 35.92,11.84 v41.66,11.84 | v43.28,11.12 45.77,8.64 50.8,8.64 VICSP.5 | v55.47,25.81 57.25,25.81 57.81,26.36 57.81,26.92 58.01,27.13 MCHIP.13 | v48.01,21.89 48.72,22.61 48.72,23.32 v51.21,25.81 51.51,26.01 51.51,29.92 51.92,30.33 51.92,35.51 49.73,37.69 49.73,43.03 v49.63,43.13 | J6.2 53.09,49.53 v53.09,43.84
  Bottom 0.203: v27.89,13.51 29.57,11.84 30.73,11.84 v31.55,11.02 | v43.28,11.12 42.37,11.12 v41.66,11.84 41.71,11.89 41.71,15.6 v48.01,21.89 | v55.47,25.81 55.47,25.86 52.68,25.86 52.63,25.81 v51.21,25.81 | v53.09,43.84 52.38,43.13 v49.63,43.13
GND  (via drill 0.3)
  Top 0.356: U$8.SHLD3 2.74,48.41 5.23,48.41 5.23,47.6 U$8.SHLD1 5.18,47.4 4.32,46.53 4.32,43.43 5.13,42.62 5.28,42.62 | 5.28,42.62 5.28,41.35 U$8.SHLD2 | 5.28,42.62 5.28,43.03 5.38,43.13 U$8.G | U$8.SHLD4 2.74,40.49 5.13,40.49 5.13,41.25 U$8.SHLD2 | 12.5,28.85 12.5,35.56 D50.1 12.34,35.61 9.45,35.61 9.25,35.81 9.25,36.27 5.18,40.34 U$8.SHLD2 | 12.5,28.85 12.5,28.8 | 12.5,28.8 12.5,28.14 12.29,27.94 C1.2 | C20.2 21.59,28.8 12.5,28.8 | C43.2 v67.31,20.32 C45.1 | 68.58,25.91 69.65,25.91 Q40.4 | 68.58,25.91 68.58,26.62 67.77,27.43 67.51,27.43 Q40.2 | C45.1 67.41,22.15 68.58,23.32 68.58,25.91 | 61.67,22.45 61.67,22.91 61.98,23.22 62.69,23.22 MCHIP.5 | 61.67,22.45 61.67,22.05 62.03,21.69 62.69,21.69 MCHIP.3 | MCHIP.21 54.15,22.45 v57.86,22.45 61.67,22.45 | C35.1 40.64,45.31 v39.17,45.31 37.64,45.31 37.64,45.52 Q30.4 37.59,45.16 36.63,44.2 36.63,43.94 36.07,43.38 Q30.2 | C24.1 33.48,16.51 v34.7,17.73 35.36,18.39 35.36,20.78 Q20.4 | 12.95,3.2 12.09,2.34 10.87,2.34 IC1.1 | 12.95,3.2 13.97,4.22 C2.2 | 18.16,49.15 17.37,48.36 17.37,45.72 C50.2 | 18.16,49.15 19.05,50.04 L2.C | C25.1 33.43,25.4 33.22,25.2 v33.22,23.82 33.22,22.4 Q20.2 | 27.38,17.88 28.4,17.88 VCHIP.3 | 27.38,17.88 27.38,19.1 27.69,19.41 28.4,19.41 VCHIP.5 | v17.78,7.21 19.05,7.21 R75.1 | v24.49,8.43 24.49,7.57 24.13,7.21 R73.1 | v29.06,8.43 29.06,7.37 29.21,7.21 R74.1 | C21.2 v22.86,12.29 | C30.2 v24.13,33.43 | v18.64,43.13 18.64,41.91 C51.2 | v34.24,43.59 33.02,43.59 C34.1 | C44.1 72.39,25.81 72.75,25.45 72.75,21.18 U1.3 | IR2.GND 73.97,35.26 73.97,36.68 74.93,37.64 R1.2 | v21.18,18.69 19.86,18.69 VCHIP.21 | v39.78,31.34 39.78,30.02 PCHIP.21 39.78,29.82 39.78,27.38 v39.47,27.08
  Top 0.356: v38.96,37.24 38.96,38.56 PCHIP.5 | v40.59,39.93 40.59,38.61 PCHIP.3 | v13.82,39.73 13.82,40.95 D51.1 | v27.08,17.27 27.28,17.48 27.28,17.68 27.33,17.73 27.38,17.88 | 18.16,49.15 v18.09,49.23 | 12.95,3.2 v12.85,3.3 | 12.5,28.85 4.27,28.85 4.27,27.33 X2.A2 | v23.62,16.66 23.27,17.02 v23.27,20.42 | v47.19,45.31 v47.19,43.69 | v66.09,23.27 67.21,22.15 C45.1
  pour Bottom: 1.27,52.07 80.01,52.07 80.01,1.27 1.27,1.27
KBCLK  (via drill 0.3)
  Top 0.203: v21.74,16.76 21.59,16.92 21.59,17.02 19.86,17.02 VCHIP.23 | v18.09,16.31 18.49,15.9 18.49,12.6 v20.22,10.87
  Bottom 0.203: v21.74,16.76 21.74,16.97 20.78,16.97 20.78,17.58 v18.09,16.31 | v20.22,10.87 21.84,9.25 25.45,9.25 26.67,8.03 28.35,8.03 28.75,7.62 33.93,7.62 41.3,14.99 41.3,23.06 46.94,23.06 47.6,23.72 53.95,23.72 55.27,22.4 56.79,22.4 58.32,20.88 63.4,20.88 63.75,20.52 64.47,20.52 64.77,20.83 66.7,20.83 67,21.13 70.26,21.13 U1.5
KBDATA  (via drill 0.3)
  Top 0.203: v25.3,10.26 24.33,11.23 24.33,13.11 21.59,13.11 20.73,13.97 20.73,15.34 19.86,16.2 VCHIP.24 | v33.07,9.5 36.02,9.5 40.34,5.18 v47.24,5.18 | v70.05,9.96 74.32,14.22 74.32,19.2 v74.57,19.46
  Bottom 0.203: v25.3,10.26 26.06,9.5 v33.07,9.5 | v47.24,5.18 48.21,4.22 48.97,4.22 49.58,3.61 49.58,3.56 53.95,3.56 53.95,3.86 54.61,3.86 55.52,4.78 64.87,4.78 v70.05,9.96 | v74.57,19.46 74.57,19.36 73.05,19.36 72.8,19.1 U1.1
MISO  (via drill 0.3)
  Top 0.203: 44.2,47.85 50.8,47.85 R32.1 | 44.2,47.85 J6.5 | v53.95,27.13 55.58,27.13 MCHIP.16 | v52.32,26.62 52.02,26.31 v51.61,21.13 | v57.45,15.7 59.84,13.31 59.84,6.71 v59.44,6.3 | v57.45,5.99 55.88,7.57 MICSP.1 | v25.04,4.37 36.47,4.37 39.73,1.12 52.32,1.12 52.32,5.64 v53.8,7.11 | v40.59,42.16 40.69,42.16 41.45,42.93 41.45,45.11 44.2,47.85 | v47.5,37.24 47.19,36.93 47.19,33.07 v45.97,31.85 | v48.31,29.57 50.7,27.18 v50.7,26.98
  Bottom 0.203: v53.95,27.13 53.44,26.62 v52.32,26.62 52.27,26.67 51,26.67 v50.7,26.98 | v51.61,21.13 51.61,21.03 51.56,20.78 51.56,19.71 52.02,19.71 56.03,15.7 v57.45,15.7 | v59.44,6.3 59.13,5.99 v57.45,5.99 | v25.04,4.37 25.04,5.79 U$9.7 | v53.8,7.11 54.25,7.57 55.83,7.57 MICSP.1 | v40.59,42.16 45.52,37.24 v47.5,37.24 | v45.97,31.85 45.97,31.6 46.18,31.39 46.23,31.39 46.23,31.34 46.28,31.34 46.28,31.29 46.33,31.29 46.33,31.24 46.38,31.24 46.38,29.82 46.43,29.82 46.69,29.57 v48.31,29.57
MOSI  (via drill 0.3)
  Top 0.203: 50.09,44.76 49.43,45.41 49.43,46.13 48.62,46.94 v48.62,47.04 | 50.09,44.76 50.8,44.04 R31.1 | v46.99,48.67 46.74,48.92 J6.4 | 41.05,23.82 41.05,24.69 42.16,25.81 v46.28,25.81 | 41.05,23.82 41.05,23.52 36.93,19.41 36.93,15.7 31.19,15.7 28.3,12.8 28.3,9.45 24.38,9.45 23.67,8.74 23.67,8.43 22.81,8.43 21.59,7.21 R70.2 | v52.32,27.79 51.92,28.19 51.92,29.72 52.38,30.18 | 52.38,30.18 52.43,30.23 53.54,30.23 53.54,29.16 54.61,28.09 56.39,28.09 56.39,27.18 MCHIP.15 | MICSP.4 57.81,10.77 57.81,11.38 56.95,12.24 v55.73,12.24 | v53.7,12.29 49.02,16.97 47.55,16.97 47.55,17.48 v47.24,17.78 | v46.08,18.85 41.1,23.82 41.05,23.82 | v48.92,42.42 48.82,42.52 48.82,43.48 50.09,44.76 | v52.32,37.95 52.32,30.23 52.38,30.18
  Bottom 0.203: v48.62,47.04 v46.99,48.67 | v46.28,25.81 48.26,27.79 v52.32,27.79 | v55.73,12.24 55.68,12.29 v53.7,12.29 | v47.24,17.78 46.18,18.85 v46.08,18.85 | v48.92,42.42 49.43,41.91 52.07,41.91 54.15,39.83 54.15,38.2 52.83,38.2 52.58,37.95 v52.32,37.95
MOSI33  (via drill 0.3)
  Top 0.203: R73.2 24.13,5.49 21.59,5.49 R70.1 21.54,5.44 21.54,5.28 v20.62,4.37
  Bottom 0.203: v20.62,4.37 20.62,5.79 U$9.3
N$2
  Top 0.203: IR1.K 78.74,39.83 74.93,36.02 R1.1
N$3
  Top 0.203: L2.A 19.05,51.56 21.59,51.56 R53.2
N$4
  Top 0.203: 35.1,45.31 36.02,45.31 36.02,45.52 Q30.1 | 35.1,45.31 33.02,45.31 C34.2 | PCHIP.8 36.52,38.61 36.32,38.81 36.32,41.3 35.1,42.52 35.1,45.31
N$5
  Top 0.203: C1.1 10.62,27.94 10.62,26.62 11.84,25.4 R4.1 11.43,25.7 X2.B2
N$8
  Top 0.203: F1.1 6.4,47.7 6.4,46.38 5.79,45.77 5.44,45.77 U$8.V
N$9  (via drill 0.3)
  Top 0.203: v22.76,16.1 22.76,19.56 20.78,21.54 20.78,22.15 21.13,22.5 21.13,23.16 21.29,23.32 VCHIP.16 | v32.26,10.31 35.81,10.31 39.32,6.81 43.08,6.81 43.43,6.45 45.72,6.45 VICSP.1
  Bottom 0.203: v22.76,16.1 28.65,10.21 32.16,10.21 v32.26,10.31
N$10
  Top 0.203: C24.2 35.15,16.51 36.42,17.78 36.42,21.49 35.56,22.35 35.41,22.35 Q20.1 35.46,22.45 35.46,23.98 36.02,24.54 36.02,26.21 32.77,26.21 28.45,21.89 VCHIP.8
N$11
  Top 0.203: C25.2 35.1,25.4 34.24,24.54 34.24,21.69 33.38,20.83 33.22,20.83 Q20.3 33.22,20.93 33.22,21.03 28.45,21.03 VCHIP.7
N$12
  Top 0.203: R20.2 12.24,15.9 10.36,17.78 10.36,20.32 D20.3
N$13  (via drill 0.3)
  Top 0.203: v22.3,21.13 23.52,22.35 23.52,23.11 23.72,23.32 VCHIP.13 | v18.09,18.69 17.22,17.83 17.22,12.34 13.82,8.94 D21.1
  Bottom 0.203: v22.3,21.13 19.86,18.69 v18.09,18.69
N$14
  Top 0.203: R21.1 12.24,13.31 11.63,12.7 11.63,9.86 D21.3
N$15
  Top 0.203: R20.1 10.62,15.85 10.62,13.36 R21.2 10.52,13.26 9.04,11.79 9.04,9.35 X2.B1
N$23
  Top 0.203: C35.2 40.64,43.59 37.64,43.59 37.64,43.38 Q30.3 37.54,43.33 37.54,38.76 37.39,38.61 PCHIP.7
N$24  (via drill 0.3)
  Top 0.203: v13.31,22.61 19.1,22.61 19.81,21.89 VCHIP.17 | v12.19,23.72 9.6,21.13 6.66,21.13 6.66,5.28 5.79,4.42 5.79,3.2 7.52,1.47 37.19,1.47 v37.19,2.54 | v40.64,5.99 48.26,5.99 VICSP.3
  Bottom 0.203: v12.19,23.72 v13.31,22.61 | v37.19,2.54 v40.64,5.99
N$28
  Top 0.203: C44.2 72.39,27.48 69.7,27.48 Q40.1 69.6,27.53 69.6,28.4 65.43,28.4 62.74,25.7 MCHIP.8
N$29
  Top 0.203: 67.46,24.89 67.46,25.86 Q40.3 | 67.46,24.89 67.46,23.88 67.31,23.72 C45.2 | MCHIP.7 62.74,24.89 67.46,24.89
N$30
  Top 0.203: J4.1 62.03,2.54 57.4,7.16 57.4,11.18 55.68,11.18 54.91,11.94 54.91,19.25 55.07,19.41 55.07,20.83 54.15,20.83 MCHIP.23
N$31
  Top 0.203: J4.2 66.04,1.52 62.43,1.52 60.4,3.56 58.47,3.56 54.51,7.52 54.51,19.66 54.15,20.02 MCHIP.24
N$32  (via drill 0.3)
  Top 0.203: v59.03,11.89 55.83,15.09 55.83,18.34 55.63,18.54 MCHIP.25 | v62.84,11.94 68.58,6.2 J4.3
  Bottom 0.203: v59.03,11.89 59.08,11.94 v62.84,11.94
N$33  (via drill 0.3)
  Top 0.203: v59.03,13.01 56.59,15.44 56.59,18.39 56.44,18.54 MCHIP.26 | v62.84,13.01 68.83,13.01 68.83,6.55 71.12,4.27 J4.4
  Bottom 0.203: v59.03,13.01 v62.84,13.01
N$34  (via drill 0.3)
  Top 0.203: v60.4,16.41 58.83,16.41 57.4,17.83 57.4,18.39 57.25,18.54 MCHIP.27 | v68.94,14.63 69.24,14.33 69.24,6.96 J4.5
  Bottom 0.203: v60.4,16.41 60.55,16.26 63.14,16.26 63.35,16.05 67.21,16.05 68.22,17.07 68.83,17.07 69.34,16.56 69.34,14.63 v68.94,14.63
N$35  (via drill 0.3)
  Top 0.203: v59.38,20.07 58.93,20.07 58.22,19.36 58.22,18.75 58.06,18.59 MCHIP.28 | v75.49,9.04 76.2,8.33 J4.6
  Bottom 0.203: v59.38,20.07 59.44,20.12 64.82,20.12 64.82,20.27 66.24,20.27 70.56,15.95 71.17,15.95 71.22,15.9 71.22,13.06 71.48,13.06 v75.49,9.04
N$37  (via drill 0.3)
  Top 0.203: v26.82,50.04 27.94,48.92 R2.1
  Bottom 0.203: v26.82,50.04 27.94,50.04 L1.A
PIXEL1  (via drill 0.3)
  Top 0.203: v21.59,21.84 21.95,22.2 21.95,23.16 22.1,23.32 VCHIP.15 | 16.1,19.41 v18.49,21.79 | 16.1,19.41 12.55,19.41 D20.1 | v46.53,12.09 42.47,12.09 42.47,12.14 41.96,12.65 33.73,12.65 33.73,12.6 32.97,11.84 29.62,11.84 29.62,8.99 30.07,8.53 30.07,6.55 29.87,6.35 27.94,6.35 v27.94,6.5 | v16.41,13.56 16.15,13.82 16.15,19.36 16.1,19.41
  Bottom 0.203: v21.59,21.84 21.54,21.79 v18.49,21.79 | VICSP.4 48.26,10.72 47.65,10.72 47.65,11.43 47.19,11.43 v46.53,12.09 | v27.94,6.5 26.82,7.62 23.62,7.62 22.4,8.13 21.13,8.13 17.98,10.87 16.41,12.45 v16.41,13.56
PMISO  (via drill 0.3)
  Top 0.203: v49.63,47.04 49.63,47.14 49.84,47.14 50.8,46.18 R32.2 | v38.71,48.97 37.13,47.4 28.8,47.4 28.8,47.19 28.6,46.99 26.67,46.99 PICSP.4 27.69,42.16 27.69,37.24 28.65,36.27 28.65,33.53 v30.99,31.19 | v36.42,31.39 36.42,31.5 35.71,32.21 35.71,32.26 35.1,32.26 PCHIP.15
  Bottom 0.203: v49.63,47.04 49.38,47.3 49.38,48.97 48.26,48.97 47.75,49.48 46.48,49.48 46.48,49.33 46.13,49.33 45.77,48.97 v38.71,48.97 | v36.42,31.39 36.32,31.29 34.14,31.29 32.92,30.07 32.11,30.07 v30.99,31.19
PMOSI  (via drill 0.3)
  Top 0.203: v50.55,41.1 50.55,42.06 50.8,42.32 R31.2 | v48.92,39.78 49.33,39.37 49.33,34.09 46.13,30.89 v45.57,30.89 | v35.56,30.48 35.1,30.94 35.1,31.45 PCHIP.16 | PICSP.1 26.16,38.61 26.16,33.43 v25.76,33.02
  Bottom 0.203: v50.55,41.1 49.23,39.78 v48.92,39.78 | v45.57,30.89 45.16,30.48 v35.56,30.48 34.75,29.67 29.11,29.67 v25.76,33.02
PSCK  (via drill 0.3)
  Top 0.203: v55.07,33.63 56.59,35.15 56.59,38 57.96,39.37 R30.2 | v51.1,35.1 49.43,33.58 49.43,32.41 46.38,29.36 v46.38,28.35 | v36.58,28.6 36.58,29.97 PCHIP.17 36.52,29.67 34.95,29.67 v32.61,32 | v30.99,36.27 31.04,36.22 v31.04,34.65
  Bottom 0.203: v55.07,33.63 55.02,33.58 v51.1,35.1 | v46.38,28.35 46.13,28.6 v36.58,28.6 | PICSP.3 26.67,38.35 28.91,38.35 v30.99,36.27 | v31.04,34.65 31.9,33.78 31.9,32 v32.61,32
SCK  (via drill 0.3)
  Top 0.203: 55.63,35.31 54.25,33.93 54.25,29.57 v54.36,29.46 | 55.63,35.31 56.19,35.87 56.19,39.27 56.29,39.37 R30.1 | v52.73,29.41 53.14,29.01 53.14,26.67 54.1,25.7 MCHIP.17 | v31.34,14.73 30.84,14.73 29.21,13.11 29.21,9.75 26.67,7.21 R71.2 | v30.23,15.85 30.18,15.9 v30.18,20.22 | v26.16,25.09 26.57,25.5 26.57,35.61 v27.38,36.42 | v28.5,37.54 28.09,37.95 28.09,44.6 27.94,44.76 R2.2 27.99,45.77 29.21,46.99 37.85,46.99 J6.6 41.71,50.85 41.71,52.22 49.33,52.22 50.29,51.26 50.29,50.24 51.66,48.87 51.66,41.2 v52.07,40.79 | v46.58,13.11 34.14,13.11 v34.14,13.46 | v53.34,39.52 53.54,39.32 53.54,37.39 55.63,35.31
  Bottom 0.203: v54.36,29.46 54.3,29.41 v52.73,29.41 | v30.23,15.85 v31.34,14.73 31.39,14.68 32.92,14.68 v34.14,13.46 | v30.18,20.22 26.16,24.23 v26.16,25.09 | v27.38,36.42 v28.5,37.54 | MICSP.3 58.42,8.18 57.51,8.18 57.51,8.64 54.15,8.64 52.58,10.21 52.58,13.11 v46.58,13.11 | v52.07,40.79 v53.34,39.52
SCK33  (via drill 0.3)
  Top 0.203: R74.2 29.21,5.49 26.67,5.49 R71.1 26.62,5.59 26.62,6.35 23.47,6.35 23.27,6.55 23.27,6.86 v22.86,7.26
  Bottom 0.203: v22.86,7.26 22.86,5.84 U$9.5
SS  (via drill 0.3)
  Top 0.203: v58.01,32.05 57.4,31.45 57.4,27.33 57.25,27.18 MCHIP.14 | v62.43,40.54 v62.43,35.97 | v53.54,42.27 52.07,43.74 52.07,49.07 50.7,50.44 v50.7,51.97 | v12.24,7.26 12.24,7.21 16.51,7.21 R72.2 | v11.12,8.38 11.63,8.38 12.24,8.99 12.75,8.99 12.75,12.29 13.11,12.65 13.11,17.12 11.48,18.75 11.48,21.89 13.56,23.98 v19.81,23.98 | v27.79,26.92 31.24,30.38 31.65,30.38 31.65,30.73 31.8,30.89 31.8,32.31 32.56,33.07 32.72,33.07 | 32.72,33.07 35.05,33.07 PCHIP.14 | J6.3 47.75,50.8 47.75,51.26 47.19,51.82 42.67,51.82 42.67,50.34 38.91,46.58 32.21,46.58 v32.21,41.91 | 32.72,33.07 v32.72,33.02
  Bottom 0.203: v58.01,32.05 58.06,32.11 59.54,32.11 61.67,34.24 61.67,35.26 v62.43,35.97 | v62.43,40.54 60.71,42.27 v53.54,42.27 | v50.7,51.97 50.7,52.07 49.73,52.07 49.73,50.8 J6.3 | v12.24,7.26 v11.12,8.38 | v19.81,23.98 20.42,24.59 22.76,24.59 25.09,26.92 v27.79,26.92 | v32.21,41.91 32.21,36.22 32.72,35.71 v32.72,33.02
SS33  (via drill 0.3)
  Top 0.203: R72.1 16.51,5.49 19.05,5.49 R75.2 19.1,5.59 19.91,6.4 19.91,7.57 v20.27,7.92
  Bottom 0.203: v20.27,7.92 19.56,7.92 19.56,6.25 U$9.2
USB_D+  (via drill 0.3)
  Top 0.203: v22.3,36.83 15.6,36.83 13.06,39.37 R51.2 | v29.46,33.83 35.05,33.83 35.05,33.88 PCHIP.13 35.15,33.83 35.71,33.83 36.02,33.53 36.02,33.02 v36.52,32.51 | v38.2,31.75 39.78,33.33 39.78,37.08 43.64,37.08 PCHIP.32
  Bottom 0.203: v22.3,36.83 25.3,33.83 v29.46,33.83 | v38.2,31.75 38.15,31.8 37.13,31.8 36.52,32.41 v36.52,32.51
USB_D-  (via drill 0.3)
  Top 0.203: v23.32,46.08 22.3,45.06 22.3,41.1 16.26,41.1 15.95,41.4 15.95,44.45 R50.2 | v28.8,45.01 31.19,45.01 31.19,41.81 31.9,41.1 35.92,41.1 35.92,37.64 36.02,37.54 36.02,35.05 35.66,34.7 35.1,34.7 PCHIP.12
  Bottom 0.203: v23.32,46.08 24.64,47.4 26.42,47.4 v28.8,45.01

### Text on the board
tPlace: Tvikia | zc19a | bcg | 1 | 1 | 1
